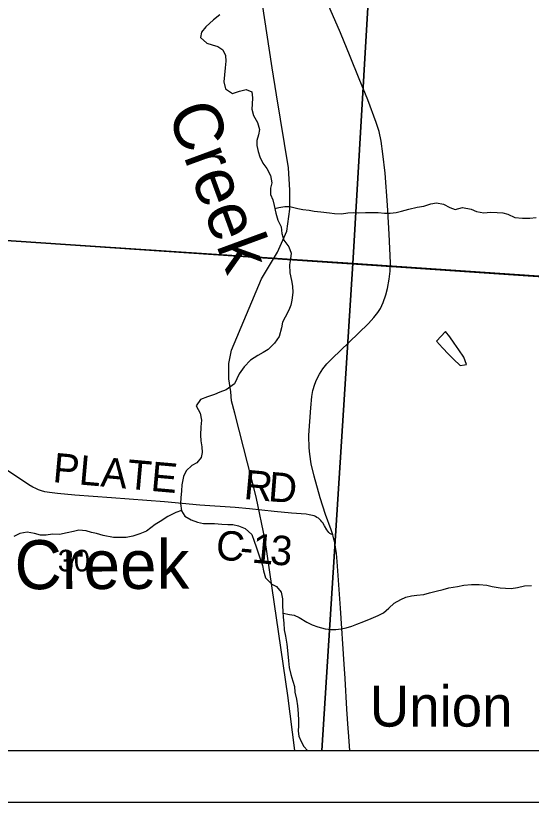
# Model space of a CAD drawing. Extents: x 39.8 to 73.8, y 13 to 35.
# Drawn here: x 44.581 to 45.577, y 26.965 to 28.484 of the extents above; entities that cross this region are included whole.
import ezdxf

# ---------------------------------------------------------------- set-up
doc = ezdxf.new("R2010")
doc.units = 0
for name, color, linetype in [('GM_X_Corporation', 7, 'Continuous'), ('GM_X_County_Road', 7, 'Continuous'), ('GM_X_County_Road_Text', 7, 'Continuous'), ('GM_X_Minor_Lake', 7, 'Continuous'), ('GM_X_Minor_River', 7, 'Continuous'), ('GM_X_Minor_River_Text', 7, 'Continuous'), ('GM_X_Rail_Line', 7, 'Continuous'), ('GM_X_Section_Text', 7, 'Continuous'), ('GM_X_State_Route', 7, 'Continuous'), ('GM_X_Unincorporated_Text', 7, 'Continuous'), ('SH_Data', 7, 'Continuous')]:
    doc.layers.add(name, color=color, linetype=linetype)

msp = doc.modelspace()

# ---------------------------------------------------------------- linework, layer by layer
at = {"layer": 'GM_X_Corporation'}
msp.add_lwpolyline([(43.3304, 29.7365), (43.2726, 28.9503), (43.2721, 28.9438), (43.2131, 28.1416), (43.9992, 28.0883), (44.127, 28.0796), (44.1422, 28.0786), (45.3064, 27.9996), (46.1767, 27.9406), (46.6011, 27.9118), (46.7316, 27.9029), (46.7775, 27.8998), (46.7905, 27.899), (47.095, 27.8783), (47.5149, 27.8498)], dxfattribs=at)
for points in [[(44.3, 29.0715), (45.2916, 29.0179), (45.2324, 28.0059), (44.237, 28.0712)], [(45.2916, 29.0179), (46.2858, 28.9647), (46.2452, 27.9368), (45.2324, 28.0059)], [(43.1433, 27.065), (48.663, 27.065), (48.663, 27.7809), (47.5414, 27.8484), (47.5149, 27.8498), (47.095, 27.8783), (46.7905, 27.899), (46.7775, 27.8998), (46.7316, 27.9029), (46.6011, 27.9118), (46.1767, 27.9406), (45.3064, 27.9996), (44.1422, 28.0786), (44.127, 28.0796), (43.9992, 28.0883), (43.2131, 28.1416)], [(44.1682, 27.065), (45.172, 27.065), (45.2324, 28.0059), (44.237, 28.0712), (44.2308, 28.0712)], [(45.172, 27.065), (46.1609, 27.065), (46.2452, 27.9368), (45.2324, 28.0059)]]:
    msp.add_lwpolyline(points, close=True, dxfattribs=at)
at = {"layer": 'GM_X_County_Road'}
msp.add_lwpolyline([(45.1933, 27.4816), (45.1905, 27.4825), (45.1877, 27.484), (45.1856, 27.4862), (45.1839, 27.4885), (45.1822, 27.491), (45.1776, 27.499), (45.1743, 27.5044), (45.1724, 27.5069), (45.1703, 27.5093), (45.168, 27.5115), (45.1656, 27.5135), (45.1629, 27.5153), (45.1601, 27.5168), (45.1572, 27.518), (45.1542, 27.519), (45.148, 27.5204), (45.1418, 27.5212), (45.1139, 27.5236), (45.0799, 27.5265), (45.0322, 27.5315), (45.0045, 27.534), (44.9363, 27.5391), (44.8682, 27.5451), (44.766, 27.5527), (44.695, 27.5582), (44.6612, 27.5613), (44.6459, 27.5632), (44.6368, 27.5649), (44.6308, 27.5665), (44.625, 27.5684), (44.6194, 27.5708), (44.6139, 27.5736), (44.606, 27.5784), (44.5649, 27.6058)], dxfattribs=at)
at = {"layer": 'GM_X_Minor_Lake'}
for p, q in [((45.411, 27.8741), (45.3938, 27.8554)), ((45.4194, 27.8639), (45.411, 27.8741)), ((45.4278, 27.8519), (45.4194, 27.8639)), ((45.3938, 27.8554), (45.4052, 27.843)), ((45.437, 27.8387), (45.4278, 27.8519)), ((45.4052, 27.843), (45.4174, 27.8306)), ((45.4466, 27.8244), (45.437, 27.8387)), ((45.4174, 27.8306), (45.427, 27.8208)), ((45.427, 27.8208), (45.4396, 27.8088)), ((45.4517, 27.8108), (45.4466, 27.8244)), ((45.4396, 27.8088), (45.4478, 27.8102)), ((45.4478, 27.8102), (45.4517, 27.8108))]:
    msp.add_line(p, q, dxfattribs=at)
at = {"layer": 'GM_X_Minor_River'}
for p, q in [((45.3692, 28.1166), (45.3827, 28.1209)), ((45.3827, 28.1209), (45.3937, 28.1229)), ((45.3937, 28.1229), (45.4077, 28.1204)), ((45.4077, 28.1204), (45.4199, 28.114)), ((45.0814, 28.1117), (45.0892, 28.1137)), ((45.0892, 28.1137), (45.1009, 28.1157)), ((45.1009, 28.1157), (45.1107, 28.1158)), ((45.1107, 28.1158), (45.1259, 28.1118)), ((45.1259, 28.1118), (45.1358, 28.1099)), ((45.1358, 28.1099), (45.1479, 28.1085)), ((45.1479, 28.1085), (45.1577, 28.1067)), ((45.1577, 28.1067), (45.1706, 28.1057)), ((45.1706, 28.1057), (45.1869, 28.1036)), ((45.3159, 28.104), (45.3261, 28.1064)), ((45.3261, 28.1064), (45.3405, 28.1107)), ((45.3405, 28.1107), (45.3567, 28.1142)), ((45.3567, 28.1142), (45.3692, 28.1166)), ((45.4199, 28.114), (45.4298, 28.11)), ((45.4298, 28.11), (45.4441, 28.1135)), ((45.4441, 28.1135), (45.4608, 28.1103)), ((45.4608, 28.1103), (45.471, 28.1062)), ((45.471, 28.1062), (45.4854, 28.1037)), ((45.1869, 28.1036), (45.1968, 28.1022)), ((45.1968, 28.1022), (45.21, 28.1015)), ((45.21, 28.1015), (45.2225, 28.1032)), ((45.2225, 28.1032), (45.2331, 28.104)), ((45.2331, 28.104), (45.244, 28.1034)), ((45.244, 28.1034), (45.2569, 28.1039)), ((45.2569, 28.1039), (45.2811, 28.1041)), ((45.2811, 28.1041), (45.2936, 28.1027)), ((45.2936, 28.1027), (45.3042, 28.1028)), ((45.3042, 28.1028), (45.3159, 28.104)), ((45.4854, 28.1037), (45.4983, 28.1045)), ((45.4983, 28.1045), (45.5111, 28.1043)), ((45.5111, 28.1043), (45.5221, 28.1036)), ((45.5221, 28.1036), (45.532, 28.1007)), ((45.532, 28.1007), (45.5453, 28.0943)), ((45.5453, 28.0943), (45.5601, 28.093)), ((45.5601, 28.093), (45.5744, 28.0931)), ((45.5744, 28.0931), (45.5865, 28.0943)), ((44.9013, 27.5283), (44.8904, 27.5249)), ((44.8746, 27.5168), (44.8599, 27.5072)), ((44.8904, 27.5249), (44.8746, 27.5168)), ((44.8501, 27.5014), (44.8336, 27.4884)), ((44.8599, 27.5072), (44.8501, 27.5014)), ((44.5884, 27.4843), (44.5768, 27.4781)), ((44.6028, 27.487), (44.5884, 27.4843)), ((44.6168, 27.4841), (44.6028, 27.487)), ((44.6289, 27.4812), (44.6168, 27.4841)), ((44.652, 27.4826), (44.6395, 27.4809)), ((44.6656, 27.4819), (44.652, 27.4826)), ((44.68, 27.4855), (44.6656, 27.4819)), ((44.6925, 27.4879), (44.68, 27.4855)), ((44.703, 27.4906), (44.6925, 27.4879)), ((44.717, 27.4892), (44.703, 27.4906)), ((44.7273, 27.4859), (44.717, 27.4892)), ((44.7371, 27.4841), (44.7273, 27.4859)), ((44.75, 27.48), (44.7371, 27.4841)), ((44.8204, 27.4833), (44.8072, 27.4787)), ((44.8336, 27.4884), (44.8204, 27.4833)), ((44.6395, 27.4809), (44.6289, 27.4812)), ((44.7697, 27.4764), (44.75, 27.48)), ((44.7811, 27.4762), (44.7697, 27.4764)), ((44.7943, 27.4763), (44.7811, 27.4762)), ((44.8072, 27.4787), (44.7943, 27.4763)), ((45.393, 27.3726), (45.4066, 27.3761)), ((45.4066, 27.3761), (45.418, 27.3792)), ((45.418, 27.3792), (45.4342, 27.382)), ((45.4342, 27.382), (45.4467, 27.3844)), ((45.4467, 27.3844), (45.4614, 27.3853)), ((45.4614, 27.3853), (45.4765, 27.3855)), ((45.4765, 27.3855), (45.4909, 27.3841)), ((45.4909, 27.3841), (45.5015, 27.3815)), ((45.5015, 27.3815), (45.5171, 27.379)), ((45.5171, 27.379), (45.5273, 27.3783)), ((45.5273, 27.3783), (45.5379, 27.3777)), ((45.5379, 27.3777), (45.5507, 27.3801)), ((45.5507, 27.3801), (45.564, 27.3829)), ((45.564, 27.3829), (45.5776, 27.3837)), ((45.3247, 27.3564), (45.3349, 27.3611)), ((45.3349, 27.3611), (45.3454, 27.3634)), ((45.3454, 27.3634), (45.3557, 27.3647)), ((45.3557, 27.3647), (45.3696, 27.3663)), ((45.3696, 27.3663), (45.3806, 27.3694)), ((45.3806, 27.3694), (45.393, 27.3726)), ((45.3018, 27.3399), (45.3123, 27.3495)), ((45.3123, 27.3495), (45.3247, 27.3564)), ((45.2811, 27.3257), (45.2912, 27.3307)), ((45.2912, 27.3307), (45.3018, 27.3399)), ((45.0973, 27.3303), (45.1097, 27.3279)), ((45.1097, 27.3279), (45.1191, 27.3265)), ((45.1191, 27.3265), (45.1286, 27.3217)), ((45.1286, 27.3217), (45.1431, 27.3131)), ((45.2532, 27.3141), (45.2679, 27.3199)), ((45.2679, 27.3199), (45.2811, 27.3257)), ((45.1431, 27.3131), (45.1533, 27.3079)), ((45.1533, 27.3079), (45.1647, 27.3038)), ((45.1647, 27.3038), (45.1788, 27.3001)), ((45.1788, 27.3001), (45.1894, 27.2987)), ((45.2098, 27.2997), (45.2196, 27.3017)), ((45.2196, 27.3017), (45.2302, 27.3052)), ((45.2302, 27.3052), (45.24, 27.309)), ((45.24, 27.309), (45.2532, 27.3141)), ((45.1894, 27.2987), (45.1992, 27.2984)), ((45.1992, 27.2984), (45.2098, 27.2997))]:
    msp.add_line(p, q, dxfattribs=at)
for points in [[(44.9751, 28.4859), (44.9627, 28.476), (44.9481, 28.4629), (44.9398, 28.4526), (44.938, 28.442), (44.9502, 28.4315), (44.9605, 28.4278), (44.9711, 28.4249), (44.981, 28.4185), (44.986, 28.4076), (44.9869, 28.3962), (44.9855, 28.3833), (44.9841, 28.3697), (44.9827, 28.3564), (44.9862, 28.3432), (44.9995, 28.3342), (45.0135, 28.3385), (45.0259, 28.3416), (45.0373, 28.3372), (45.0385, 28.3254), (45.0379, 28.3133), (45.0368, 28.3035), (45.0404, 28.2914), (45.048, 28.2782), (45.0516, 28.2642), (45.0498, 28.2543), (45.0468, 28.2433), (45.0465, 28.2338), (45.0493, 28.2221), (45.0524, 28.2115), (45.0582, 28.1994), (45.0662, 28.1893), (45.0728, 28.1753), (45.0755, 28.1617), (45.0734, 28.1514), (45.0731, 28.1386), (45.0777, 28.1287), (45.0801, 28.1178), (45.0832, 28.103), (45.0871, 28.0894), (45.0937, 28.0762), (45.0949, 28.0637), (45.0988, 28.0505), (45.1088, 28.0381), (45.113, 28.0256), (45.112, 28.0146), (45.1098, 28.0028), (45.1107, 27.9873), (45.1139, 27.9729), (45.1159, 27.962), (45.116, 27.9495), (45.1146, 27.9347), (45.1124, 27.9252), (45.1087, 27.9157), (45.1016, 27.902), (45.096, 27.8924), (45.0942, 27.8814), (45.0899, 27.8644), (45.0809, 27.8518), (45.0685, 27.8395), (45.0587, 27.8334), (45.0489, 27.8276), (45.0346, 27.8191), (45.0219, 27.8061), (45.0125, 27.7928), (45.0081, 27.7829), (45.0032, 27.773), (44.9871, 27.7619), (44.9754, 27.7568), (44.9648, 27.7526), (44.9513, 27.7483), (44.9381, 27.7432), (44.9295, 27.7306), (44.9372, 27.7167), (44.9399, 27.7031), (44.9385, 27.6902), (44.9379, 27.6743), (44.9387, 27.6633), (44.9404, 27.6512)], [(44.9404, 27.6512), (44.9408, 27.6406), (44.9394, 27.6307), (44.9308, 27.6204), (44.921, 27.6154), (44.9101, 27.6054), (44.9049, 27.5944), (44.902, 27.5781), (44.9014, 27.5667), (44.8996, 27.553), (44.8993, 27.542), (44.9013, 27.528), (44.9075, 27.5178), (44.9196, 27.5108), (44.9322, 27.5063), (44.9439, 27.5034), (44.9538, 27.5035), (44.9647, 27.5032), (44.9791, 27.5022), (44.9905, 27.5016), (45.0003, 27.5013), (45.0113, 27.4987), (45.0242, 27.4935), (45.0368, 27.4819), (45.0418, 27.4694), (45.0453, 27.4585), (45.0496, 27.4449), (45.0539, 27.4335), (45.0574, 27.4226), (45.0597, 27.412), (45.0633, 27.3984), (45.0755, 27.386), (45.085, 27.3815), (45.0938, 27.3706), (45.0965, 27.3581), (45.0963, 27.3453), (45.0971, 27.3331), (45.0976, 27.3225), (45.0988, 27.3112), (45.0997, 27.2979), (45.1021, 27.2858), (45.1045, 27.2703), (45.1061, 27.2578), (45.1078, 27.2381), (45.1094, 27.2252), (45.1126, 27.212), (45.1165, 27.1988), (45.1192, 27.1886), (45.1204, 27.1776), (45.1232, 27.1644), (45.1252, 27.1511), (45.1265, 27.1367), (45.127, 27.1231), (45.127, 27.1132), (45.1264, 27.1022), (45.128, 27.0924), (45.1322, 27.0826), (45.1376, 27.0724), (45.1445, 27.065)]]:
    msp.add_lwpolyline(points, dxfattribs=at)
at = {"layer": 'GM_X_Rail_Line'}
msp.add_lwpolyline([(45.1203, 27.065), (45.1065, 27.1711), (45.0625, 27.4712), (45.0453, 27.5547), (45.0044, 27.7166), (44.998, 27.7403), (44.9966, 27.7578), (44.9925, 27.7828), (44.9928, 27.8126), (44.9976, 27.8383), (45.0557, 27.9757), (45.0866, 28.0277), (45.1046, 28.0683), (45.1102, 28.1107), (45.1102, 28.147), (45.1077, 28.1905), (45.0844, 28.3312), (45.076, 28.3834), (45.0571, 28.5106), (45.0423, 28.5989), (45.0171, 28.697), (44.9949, 28.7531), (44.8323, 29.1497)], dxfattribs=at)
at = {"layer": 'GM_X_State_Route'}
for points in [[(45.1933, 27.4816), (45.1904, 27.4914), (45.1795, 27.5205), (45.1691, 27.553), (45.1574, 27.5948), (45.1518, 27.6189), (45.149, 27.6372), (45.148, 27.6494), (45.1475, 27.6557), (45.1474, 27.6666), (45.1474, 27.6742), (45.151, 27.7269), (45.153, 27.7485), (45.1551, 27.7606), (45.1585, 27.7725), (45.1618, 27.781), (45.1675, 27.792), (45.1743, 27.8022), (45.1821, 27.8118), (45.1927, 27.823), (45.2243, 27.8528), (45.2623, 27.8896), (45.2729, 27.901), (45.2805, 27.9109), (45.2854, 27.919), (45.2907, 27.9303), (45.296, 27.945), (45.2992, 27.9571), (45.3026, 27.9755), (45.3043, 27.991), (45.3047, 28.0066), (45.3025, 28.0625), (45.2992, 28.1183), (45.2945, 28.1803), (45.2904, 28.2174), (45.2868, 28.242), (45.2828, 28.2603), (45.2774, 28.2781), (45.2611, 28.3218), (45.2446, 28.3621), (45.2271, 28.4052), (45.2082, 28.4512), (45.1213, 28.6505)], [(45.2173, 27.2038), (45.2156, 27.2316), (45.2086, 27.3401), (45.2021, 27.4299), (45.2005, 27.4453), (45.1988, 27.4576), (45.1971, 27.4667), (45.195, 27.4757), (45.1941, 27.4787), (45.1933, 27.4816)], [(45.2263, 27.065), (45.2238, 27.1002), (45.2233, 27.1077), (45.2208, 27.1449), (45.2173, 27.2038)]]:
    msp.add_lwpolyline(points, dxfattribs=at)
at = {"layer": 'SH_Data'}
for p, q in [((41.863, 27.065), (48.663, 27.065)), ((41.763, 26.965), (48.763, 26.965))]:
    msp.add_line(p, q, dxfattribs=at)

# ---------------------------------------------------------------- texts
at = {"layer": 'GM_X_County_Road_Text'}
for s, height, rotation, p in [('PLATE', 0.05682, 354.906, (44.651, 27.5835)), ('R', 0.0568, 354.861, (45.0202, 27.5509)), ('D', 0.0568, 355.5266, (45.0674, 27.5467)), ('C', 0.0568, 354.7469, (44.9658, 27.4345)), ('1', 0.0568, 354.8082, (45.0356, 27.4281)), ('3', 0.0568, 355.1583, (45.0708, 27.4249)), ('-', 0.0568, 354.7518, (45.0123, 27.4303))]:
    msp.add_text(s, height=height, rotation=rotation, dxfattribs=at).set_placement(p)
at = {"layer": 'GM_X_Minor_River_Text'}
for height, rotation, p in [(0.0947, 290.1693, (44.8731, 28.2989)), (0.09469, 0.1706, (44.5785, 27.3764))]:
    msp.add_text('Creek', height=height, rotation=rotation, dxfattribs=at).set_placement(p)
at = {"layer": 'GM_X_Section_Text'}
msp.add_text('30', height=0.04186, rotation=0, dxfattribs=at).set_placement((44.662, 27.4108))
at = {"layer": 'GM_X_Unincorporated_Text'}
msp.add_text('Union', height=0.07898, rotation=0, dxfattribs=at).set_placement((45.2649, 27.1111))

doc.saveas('drawing.dxf')
